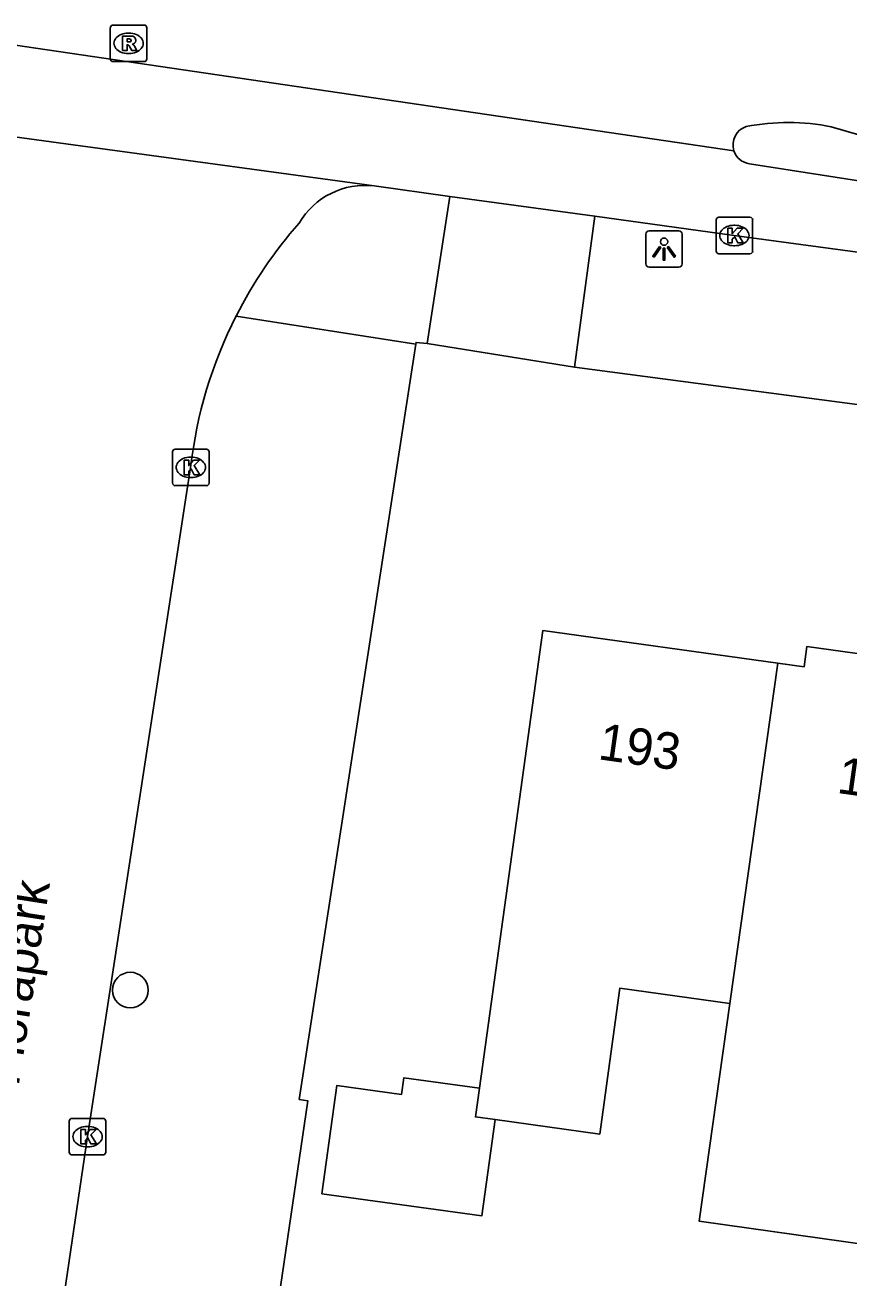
# Model space of a CAD drawing. Extents: x 161486 to 162249, y 379484 to 380829.
# Drawn here: x 161808.57 to 161831.14, y 380777.9 to 380812.21 of the extents above; entities that cross this region are included whole.
import ezdxf

# ---------------------------------------------------------------- set-up
doc = ezdxf.new("R2010")
doc.units = 0
for name, color, linetype in [('IMGEO_Boom', 7, 'Continuous'), ('IMGEO_Fietspad_open', 7, 'Continuous'), ('IMGEO_Kolk', 7, 'Continuous'), ('IMGEO_Lichtpunt', 7, 'Continuous'), ('IMGEO_Openbare_ruimte_label', 7, 'Continuous'), ('IMGEO_Pand', 7, 'Continuous'), ('IMGEO_Pand_nummerreeks', 7, 'Continuous'), ('IMGEO_Rijbaan_lokaal_gesloten', 7, 'Continuous'), ('IMGEO_Rijbaan_lokaal_open', 7, 'Continuous'), ('IMGEO_Rioolput', 7, 'Continuous'), ('IMGEO_Voetpad_open', 7, 'Continuous')]:
    doc.layers.add(name, color=color, linetype=linetype)

msp = doc.modelspace()

# ---------------------------------------------------------------- linework, layer by layer
at = {"layer": 'IMGEO_Boom'}
msp.add_circle((161811.455, 380785.78), 0.489, dxfattribs=at)
at = {"layer": 'IMGEO_Fietspad_open'}
for points in [[(161828.42, 380808.407), (161833.402, 380807.634)], [(161818.139, 380807.803), (161820.208, 380807.51)], [(161820.208, 380807.51), (161824.182, 380806.969)], [(161824.182, 380806.969), (161828.002, 380806.446), (161838.216, 380805.069)]]:
    msp.add_lwpolyline(points, dxfattribs=at)
msp.add_arc((161828.493, 380808.928), 0.526, 198.0452, 262.0013, dxfattribs=at)
at = {"layer": 'IMGEO_Kolk'}
for p, q in [((161827.505, 380806.018), (161827.505, 380806.87)), ((161827.58, 380806.944), (161828.432, 380806.944)), ((161828.506, 380806.87), (161828.506, 380806.018)), ((161827.993, 380806.724), (161828.018, 380806.724)), ((161828.016, 380806.164), (161827.991, 380806.164)), ((161828.432, 380805.944), (161827.58, 380805.944)), ((161812.688, 380800.594), (161813.54, 380800.594)), ((161812.613, 380799.668), (161812.613, 380800.52)), ((161813.101, 380800.374), (161813.126, 380800.374)), ((161813.614, 380800.52), (161813.614, 380799.668)), ((161813.54, 380799.594), (161812.688, 380799.594)), ((161813.124, 380799.814), (161813.099, 380799.814)), ((161809.783, 380781.342), (161809.783, 380782.194)), ((161809.858, 380782.268), (161810.71, 380782.268)), ((161810.784, 380782.194), (161810.784, 380781.342)), ((161810.271, 380782.048), (161810.296, 380782.048)), ((161810.294, 380781.488), (161810.269, 380781.488)), ((161810.71, 380781.268), (161809.858, 380781.268))]:
    msp.add_line(p, q, dxfattribs=at)
for points in [[(161827.505, 380806.018), (161827.505, 380806.87)], [(161827.58, 380806.944), (161828.432, 380806.944)], [(161828.506, 380806.87), (161828.506, 380806.018)], [(161827.826, 380806.644), (161827.949, 380806.644), (161827.949, 380806.493), (161828.079, 380806.644), (161828.243, 380806.644), (161828.097, 380806.493), (161828.25, 380806.244), (161828.098, 380806.244), (161828.013, 380806.408), (161827.949, 380806.341), (161827.949, 380806.244), (161827.826, 380806.244), (161827.826, 380806.644)], [(161828.432, 380805.944), (161827.58, 380805.944)], [(161812.688, 380800.594), (161813.54, 380800.594)], [(161812.613, 380799.668), (161812.613, 380800.52)], [(161812.934, 380800.294), (161813.057, 380800.294), (161813.057, 380800.143), (161813.187, 380800.294), (161813.351, 380800.294), (161813.205, 380800.143), (161813.358, 380799.894), (161813.206, 380799.894), (161813.121, 380800.058), (161813.057, 380799.991), (161813.057, 380799.894), (161812.934, 380799.894), (161812.934, 380800.294)], [(161813.614, 380800.52), (161813.614, 380799.668)], [(161813.54, 380799.594), (161812.688, 380799.594)], [(161809.783, 380781.342), (161809.783, 380782.194)], [(161809.858, 380782.268), (161810.71, 380782.268)], [(161810.784, 380782.194), (161810.784, 380781.342)], [(161810.104, 380781.968), (161810.227, 380781.968), (161810.227, 380781.817), (161810.357, 380781.968), (161810.521, 380781.968), (161810.375, 380781.817), (161810.528, 380781.568), (161810.376, 380781.568), (161810.291, 380781.732), (161810.227, 380781.665), (161810.227, 380781.568), (161810.104, 380781.568), (161810.104, 380781.968)], [(161810.71, 380781.268), (161809.858, 380781.268)]]:
    msp.add_lwpolyline(points, dxfattribs=at)
for centre, start, end in [((161827.582, 380806.868), 91.552, 178.448), ((161827.582, 380806.868), 91.552, 178.448), ((161828.43, 380806.868), 1.552, 88.448), ((161828.43, 380806.868), 1.552, 88.448), ((161827.582, 380806.02), 181.552, 268.448), ((161827.582, 380806.02), 181.552, 268.448), ((161828.43, 380806.02), 271.552, 358.448), ((161828.43, 380806.02), 271.552, 358.448), ((161812.69, 380800.518), 91.552, 178.448), ((161812.69, 380800.518), 91.552, 178.448), ((161813.538, 380800.518), 1.552, 88.448), ((161813.538, 380800.518), 1.552, 88.448), ((161812.69, 380799.67), 181.552, 268.448), ((161812.69, 380799.67), 181.552, 268.448), ((161813.538, 380799.67), 271.552, 358.448), ((161813.538, 380799.67), 271.552, 358.448), ((161809.86, 380782.192), 91.552, 178.448), ((161809.86, 380782.192), 91.552, 178.448), ((161810.708, 380782.192), 1.552, 88.448), ((161810.708, 380782.192), 1.552, 88.448), ((161809.86, 380781.344), 181.552, 268.448), ((161809.86, 380781.344), 181.552, 268.448), ((161810.708, 380781.344), 271.552, 358.448), ((161810.708, 380781.344), 271.552, 358.448)]:
    msp.add_arc(centre, 0.0765, start, end, dxfattribs=at)
for centre, major_axis, ratio, start_param, end_param in [((161827.992, 380806.444), (-0.387, 0.002), 0.722429, 4.712389, 7.853982), ((161828.017, 380806.444), (-0.39, 0.002), 0.717154, 1.570796, 4.712389), ((161813.1, 380800.094), (-0.387, 0.002), 0.722429, 4.712389, 7.853982), ((161813.125, 380800.094), (-0.39, 0.002), 0.717154, 1.570796, 4.712389), ((161810.27, 380781.768), (-0.387, 0.002), 0.722429, 4.712389, 7.853982), ((161810.295, 380781.768), (-0.39, 0.002), 0.717154, 1.570796, 4.712389)]:
    msp.add_ellipse(centre, major_axis=major_axis, ratio=ratio, start_param=start_param, end_param=end_param, dxfattribs=at)
at = {"layer": 'IMGEO_Lichtpunt'}
for p, q in [((161825.58, 380806.477), (161825.58, 380805.67)), ((161825.58, 380806.477), (161825.58, 380805.67)), ((161826.482, 380806.572), (161825.674, 380806.572)), ((161826.482, 380806.572), (161825.674, 380806.572)), ((161826.576, 380805.67), (161826.576, 380806.477)), ((161826.576, 380805.67), (161826.576, 380806.477)), ((161825.674, 380805.576), (161826.482, 380805.576)), ((161825.674, 380805.576), (161826.482, 380805.576))]:
    msp.add_line(p, q, dxfattribs=at)
for points in [[(161825.954, 380806.141), (161825.993, 380806.113), (161825.805, 380805.851), (161825.767, 380805.878), (161825.954, 380806.141)], [(161826.056, 380806.093), (161826.103, 380806.093), (161826.103, 380805.771), (161826.056, 380805.771), (161826.056, 380806.093)], [(161826.166, 380806.113), (161826.204, 380806.14), (161826.391, 380805.878), (161826.352, 380805.85), (161826.166, 380806.113)]]:
    msp.add_lwpolyline(points, dxfattribs=at)
msp.add_circle((161826.079, 380806.275), 0.0994, dxfattribs=at)
for centre, start, end in [((161825.674, 380806.477), 90, 180), ((161825.674, 380806.477), 90, 180), ((161826.482, 380806.477), 0, 90), ((161826.482, 380806.477), 0, 90), ((161825.674, 380805.67), 180, 270), ((161825.674, 380805.67), 180, 270), ((161826.482, 380805.67), 270, 0), ((161826.482, 380805.67), 270, 360)]:
    msp.add_arc(centre, 0.0946, start, end, dxfattribs=at)
at = {"layer": 'IMGEO_Pand'}
for points in [[(161829.194, 380794.735), (161822.758, 380795.628), (161821.02, 380783.091)], [(161827.879, 380785.418), (161827.038, 380779.456), (161832.359, 380778.705), (161832.633, 380780.645), (161833.779, 380780.486), (161834.94, 380788.863), (161835.627, 380793.815), (161832.87, 380794.197), (161832.951, 380794.781), (161829.991, 380795.191), (161829.914, 380794.635), (161829.194, 380794.735)], [(161827.879, 380785.418), (161829.194, 380794.735)], [(161821.449, 380782.233), (161824.317, 380781.836), (161824.871, 380785.835), (161827.879, 380785.418)], [(161821.02, 380783.091), (161818.949, 380783.378), (161818.886, 380782.925), (161817.114, 380783.17), (161816.703, 380780.205), (161821.084, 380779.598), (161821.449, 380782.233)], [(161821.449, 380782.233), (161820.911, 380782.308), (161821.02, 380783.091)]]:
    msp.add_lwpolyline(points, dxfattribs=at)
at = {"layer": 'IMGEO_Rijbaan_lokaal_gesloten'}
for points in [[(161804.89, 380812.158), (161827.993, 380808.765)], [(161830.66, 380809.424), (161833.531, 380808.591)]]:
    msp.add_lwpolyline(points, dxfattribs=at)
for centre, radius, start, end in [((161829.479, 380803.369), 6.169, 78.9672, 100.7377), ((161828.495, 380808.928), 0.528, 108.2135, 198.0377)]:
    msp.add_arc(centre, radius, start, end, dxfattribs=at)
at = {"layer": 'IMGEO_Rijbaan_lokaal_open'}
for points in [[(161818.139, 380807.803), (161805.523, 380809.521)], [(161809.183, 380774.339), (161810.279, 380781.768), (161813.109, 380800.094)]]:
    msp.add_lwpolyline(points, dxfattribs=at)
for centre, radius, start, end in [((161817.89, 380805.722), 2.096, 83.1678, 149.7396), ((161825.198, 380798.727), 12.164, 138.5591, 153.0564), ((161825.178, 380798.729), 12.146, 153.0186, 173.5448)]:
    msp.add_arc(centre, radius, start, end, dxfattribs=at)
at = {"layer": 'IMGEO_Rioolput'}
for p, q in [((161810.908, 380811.28), (161810.908, 380812.132)), ((161810.983, 380812.206), (161811.835, 380812.206)), ((161811.396, 380811.986), (161811.421, 380811.986)), ((161811.909, 380812.132), (161811.909, 380811.28)), ((161811.419, 380811.426), (161811.394, 380811.426)), ((161811.835, 380811.206), (161810.983, 380811.206))]:
    msp.add_line(p, q, dxfattribs=at)
for points in [[(161810.908, 380811.28), (161810.908, 380812.132)], [(161810.983, 380812.206), (161811.835, 380812.206)], [(161811.909, 380812.132), (161811.909, 380811.28)], [(161811.497, 380811.904), (161811.245, 380811.906), (161811.245, 380811.506)], [(161811.245, 380811.506), (161811.369, 380811.506), (161811.369, 380811.668), (161811.38, 380811.668)], [(161811.423, 380811.825), (161811.369, 380811.825), (161811.369, 380811.744)], [(161811.369, 380811.744), (161811.421, 380811.744)], [(161811.427, 380811.639), (161811.498, 380811.506), (161811.638, 380811.506), (161811.573, 380811.632)], [(161811.835, 380811.206), (161810.983, 380811.206)]]:
    msp.add_lwpolyline(points, dxfattribs=at)
for centre, radius, start, end in [((161810.985, 380812.13), 0.0765, 91.552, 178.448), ((161810.985, 380812.13), 0.0765, 91.552, 178.448), ((161811.833, 380812.13), 0.0765, 1.552, 88.448), ((161811.833, 380812.13), 0.0765, 1.552, 88.448), ((161811.379, 380811.615), 0.0533, 26.0293, 88.6989), ((161811.405, 380811.933), 0.19, 274.7715, 282.9687), ((161811.429, 380811.729), 0.0964, 77.0061, 93.1865), ((161811.443, 380811.786), 0.0378, 276.6634, 79.6772), ((161811.496, 380811.794), 0.109, 350.3612, 89.416), ((161811.494, 380811.794), 0.112, 277.5842, 350.9817), ((161811.478, 380811.579), 0.108, 29.5134, 73.7905), ((161810.985, 380811.282), 0.0765, 181.552, 268.448), ((161810.985, 380811.282), 0.0765, 181.552, 268.448), ((161811.833, 380811.282), 0.0765, 271.552, 358.448), ((161811.833, 380811.282), 0.0765, 271.552, 358.448)]:
    msp.add_arc(centre, radius, start, end, dxfattribs=at)
for centre, major_axis, ratio, start_param, end_param in [((161811.395, 380811.706), (-0.387, 0.002), 0.722429, 4.712389, 7.853982), ((161811.42, 380811.706), (-0.39, 0.002), 0.717154, 1.570796, 4.712389)]:
    msp.add_ellipse(centre, major_axis=major_axis, ratio=ratio, start_param=start_param, end_param=end_param, dxfattribs=at)
at = {"layer": 'IMGEO_Voetpad_open'}
for points in [[(161819.588, 380803.484), (161820.208, 380807.51)], [(161824.182, 380806.969), (161823.626, 380802.84)], [(161819.277, 380803.465), (161814.354, 380804.239)], [(161814.411, 380769.967), (161815.201, 380775.177), (161816.322, 380782.748), (161816.082, 380782.786), (161819.277, 380803.465)], [(161819.588, 380803.484), (161819.285, 380803.517), (161819.277, 380803.465)], [(161823.626, 380802.84), (161819.588, 380803.484)], [(161837.657, 380800.986), (161823.626, 380802.84)]]:
    msp.add_lwpolyline(points, dxfattribs=at)

# ---------------------------------------------------------------- texts
at = {"layer": 'IMGEO_Openbare_ruimte_label'}
msp.add_text('Florapark', height=1, rotation=81.1972, dxfattribs=at).set_placement((161808.393, 380783.128))
at = {"layer": 'IMGEO_Pand_nummerreeks'}
for s, rotation, p in [('193', 351.9786, (161824.243, 380792.106)), ('191', 351.9809, (161830.79, 380791.184))]:
    msp.add_text(s, height=1, rotation=rotation, dxfattribs=at).set_placement(p)

doc.saveas('drawing.dxf')
